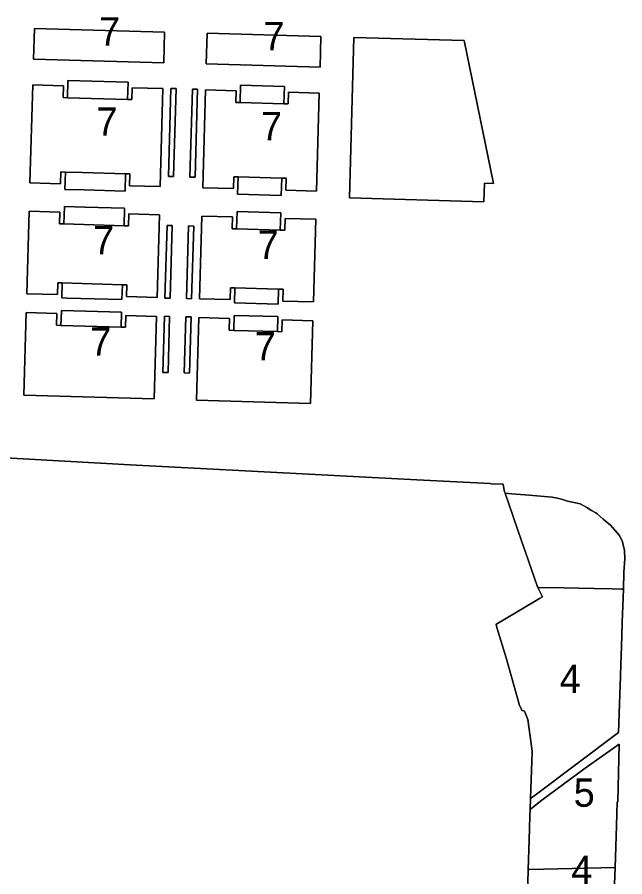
# Model space of a CAD drawing. Extents: x 598968 to 613553, y 4409678 to 4430833.
# Drawn here: x 607451 to 607708.4, y 4415273.1 to 4415637.2 of the extents above; entities that cross this region are included whole.
import ezdxf

# ---------------------------------------------------------------- set-up
doc = ezdxf.new("R2010")
doc.units = 0
for name, color, linetype in [('1', 7, 'Continuous'), ('ZONA 4. CASES UNIFAMILIRAS AÏLLADES EN PARCEL.LES', 7, 'Continuous'), ('ZONA 5. CASES UNIFAMILIARS EN RENGLE', 7, 'Continuous'), ('ZONA 7. CONJUNTS AMB ORDENACIONS ESPECÍFIQUES', 7, 'Continuous')]:
    doc.layers.add(name, color=color, linetype=linetype)

msp = doc.modelspace()

# ---------------------------------------------------------------- linework, layer by layer
at = {"layer": '1'}
for points in [[(607458.2278, 4415632.5068), (607513.3874, 4415630.9511), (607513.0173, 4415617.9598), (607457.8614, 4415619.5121)], [(607531.3978, 4415630.4394), (607579.6165, 4415629.0809), (607579.6281, 4415629.0806), (607579.2619, 4415616.0906), (607531.0172, 4415617.4505)], [(607593.6261, 4415628.6869), (607640.3951, 4415627.3559), (607652.7347, 4415566.7745), (607648.9096, 4415566.9135), (607648.6255, 4415559.0949), (607591.6906, 4415560.7152)], [(607640.3951, 4415627.3559), (607593.6261, 4415628.6869), (607591.6906, 4415560.7152), (607648.6255, 4415559.0949), (607648.9096, 4415566.9135), (607652.7347, 4415566.7745)], [(607472.4602, 4415610.4767), (607497.9495, 4415609.7512), (607497.7403, 4415602.4044), (607499.5895, 4415602.3518), (607499.7318, 4415607.3496), (607512.7264, 4415606.9798), (607511.5453, 4415565.4971), (607498.5506, 4415565.8669), (607498.693, 4415570.8648), (607496.8437, 4415570.9175), (607496.6345, 4415563.5705), (607479.4003, 4415564.0609), (607471.159, 4415564.2955), (607471.3544, 4415571.6428), (607469.5051, 4415571.6955), (607469.3628, 4415566.6976), (607456.3681, 4415567.0674), (607457.5484, 4415608.5198), (607470.5439, 4415608.1766), (607470.4017, 4415603.1824), (607472.2509, 4415603.1297)], [(607497.7403, 4415602.4044), (607497.9495, 4415609.7512), (607472.4602, 4415610.4767), (607472.2509, 4415603.1297)], [(607517.2167, 4415569.6873), (607515.0176, 4415569.75), (607516.0793, 4415607.0345), (607518.2783, 4415606.9718)], [(607518.2783, 4415606.9718), (607516.0793, 4415607.0345), (607515.0176, 4415569.75), (607517.2167, 4415569.6873)], [(607545.6296, 4415608.3943), (607564.1719, 4415607.8667), (607563.9626, 4415600.5197), (607565.8119, 4415600.4671), (607565.9542, 4415605.465), (607578.9488, 4415605.0952), (607577.7676, 4415563.6124), (607564.773, 4415563.9823), (607564.9153, 4415568.9802), (607563.0661, 4415569.0329), (607562.8569, 4415561.6859), (607544.3147, 4415562.2135), (607544.5238, 4415569.5604), (607542.6746, 4415569.6131), (607542.5323, 4415564.6153), (607529.5377, 4415564.985), (607530.7189, 4415606.4678), (607543.7134, 4415606.0979), (607543.5711, 4415601.1001), (607545.4204, 4415601.0474)], [(607563.9626, 4415600.5197), (607564.1719, 4415607.8667), (607545.6296, 4415608.3943), (607545.4204, 4415601.0474)], [(607526.313, 4415569.4285), (607524.1139, 4415569.4911), (607525.1754, 4415606.7756), (607527.3745, 4415606.713)], [(607527.3745, 4415606.713), (607525.1754, 4415606.7756), (607524.1139, 4415569.4911), (607526.313, 4415569.4285)], [(607496.8437, 4415570.9175), (607478.6707, 4415571.4346), (607471.3544, 4415571.6428), (607471.159, 4415564.2955), (607479.4003, 4415564.0609), (607496.6345, 4415563.5705)], [(607563.0661, 4415569.0329), (607544.5238, 4415569.5604), (607544.3147, 4415562.2135), (607562.8569, 4415561.6859)], [(607470.9374, 4415556.999), (607479.5455, 4415556.754), (607496.4268, 4415556.2735), (607496.2176, 4415548.9266), (607498.0668, 4415548.8739), (607498.2091, 4415553.8719), (607511.2037, 4415553.5021), (607510.2075, 4415518.5166), (607497.2129, 4415518.8865), (607497.3553, 4415523.8844), (607495.506, 4415523.9371), (607495.3253, 4415517.5897), (607472.108, 4415518.2504), (607469.8359, 4415518.3151), (607470.0167, 4415524.6624), (607468.1674, 4415524.7151), (607468.0251, 4415519.7171), (607455.0304, 4415520.087), (607456.0266, 4415555.0724), (607469.0213, 4415554.7025), (607468.879, 4415549.7046), (607470.7282, 4415549.652)], [(607496.2176, 4415548.9266), (607496.4268, 4415556.2735), (607479.5455, 4415556.754), (607470.9374, 4415556.999), (607470.7282, 4415549.652), (607479.2166, 4415549.4105)], [(607544.1069, 4415554.9166), (607562.6491, 4415554.389), (607562.4399, 4415547.042), (607564.2892, 4415546.9894), (607564.4315, 4415551.9872), (607577.426, 4415551.6175), (607576.4299, 4415516.632), (607563.4353, 4415517.0018), (607563.5776, 4415521.9997), (607561.7284, 4415522.0524), (607561.5476, 4415515.705), (607543.0054, 4415516.2327), (607543.1861, 4415522.5801), (607541.3368, 4415522.6327), (607541.1946, 4415517.6348), (607528.2, 4415518.0046), (607529.1962, 4415552.9901), (607542.1907, 4415552.6202), (607542.0485, 4415547.6223), (607543.8976, 4415547.5697)], [(607562.4399, 4415547.042), (607562.6491, 4415554.389), (607544.1069, 4415554.9166), (607543.8976, 4415547.5697)], [(607516.6275, 4415548.996), (607514.4285, 4415549.0586), (607513.5518, 4415518.2686), (607515.7509, 4415518.206)], [(607515.7509, 4415518.206), (607513.5518, 4415518.2686), (607514.4285, 4415549.0586), (607516.6275, 4415548.996)], [(607525.7237, 4415548.7371), (607523.5247, 4415548.7997), (607522.6481, 4415518.0125), (607524.8472, 4415517.95)], [(607525.7237, 4415548.7371), (607524.8472, 4415517.95), (607522.6481, 4415518.0125), (607523.5247, 4415548.7997)], [(607495.506, 4415523.9371), (607474.3119, 4415524.5402), (607470.0167, 4415524.6624), (607469.8359, 4415518.3151), (607472.108, 4415518.2504), (607495.3253, 4415517.5897)], [(607561.7284, 4415522.0524), (607543.1861, 4415522.5801), (607543.0054, 4415516.2327), (607561.5476, 4415515.705)], [(607454.8027, 4415512.0903), (607467.7975, 4415511.7204), (607467.6551, 4415506.7226), (607469.5044, 4415506.6699), (607469.6742, 4415512.6383), (607469.685, 4415513.0172), (607469.8366, 4415513.0129), (607495.1744, 4415512.2919), (607494.9937, 4415505.9446), (607496.8429, 4415505.8919), (607496.9852, 4415510.8898), (607509.9799, 4415510.52), (607508.9836, 4415475.5346), (607453.8065, 4415477.1049)], [(607494.9937, 4415505.9446), (607495.1744, 4415512.2919), (607469.8366, 4415513.0129), (607469.685, 4415513.0172), (607469.6742, 4415512.6383), (607469.5044, 4415506.6699)], [(607515.5318, 4415510.512), (607513.3327, 4415510.5747), (607512.6553, 4415486.7845), (607514.854, 4415486.709)], [(607514.854, 4415486.709), (607512.6553, 4415486.7845), (607513.3327, 4415510.5747), (607515.5318, 4415510.512)], [(607524.628, 4415510.2532), (607522.4289, 4415510.3157), (607521.7515, 4415486.5257), (607523.9507, 4415486.4654)], [(607523.9507, 4415486.4654), (607521.7515, 4415486.5257), (607522.4289, 4415510.3157), (607524.628, 4415510.2532)], [(607542.8546, 4415510.9349), (607561.3968, 4415510.4072), (607561.2161, 4415504.0599), (607563.0653, 4415504.0072), (607563.2076, 4415509.0052), (607576.2022, 4415508.6353), (607575.206, 4415473.6499), (607526.9762, 4415475.0225), (607527.9724, 4415510.0079), (607540.9669, 4415509.6381), (607540.8246, 4415504.6402), (607542.6738, 4415504.5876)], [(607561.2161, 4415504.0599), (607561.3968, 4415510.4072), (607542.8546, 4415510.9349), (607542.6738, 4415504.5876)], [(607707.7901, 4415394.9734), (607708.03, 4415402.1033), (607708.39, 4415407.8433), (607708.31, 4415411.3332), (607707.615, 4415414.3728), (607707.48, 4415414.9632), (607706.19, 4415417.7231), (607702.38, 4415422.073), (607699.2701, 4415424.6629), (607696.6286, 4415426.8626), (607696.1601, 4415427.2528), (607694.3101, 4415428.3528), (607692.3601, 4415429.5027), (607689.4202, 4415431.0626), (607683.5602, 4415432.4325), (607682.5102, 4415432.8625), (607680.3703, 4415433.3325), (607677.5903, 4415433.9823), (607667.8304, 4415434.7822), (607660.5105, 4415435.282), (607657.6822, 4415435.6), (607664.629, 4415415.4382), (607666.2658, 4415410.6878), (607671.211, 4415396.3354), (607671.5308, 4415395.6974), (607672.0125, 4415395.6878), (607672.0105, 4415395.6927), (607682.6935, 4415395.4773), (607688.9303, 4415395.3529), (607695.3387, 4415395.2302), (607703.0001, 4415395.0833), (607707.012, 4415394.9913)]]:
    msp.add_lwpolyline(points, close=True, dxfattribs=at)
for points in [[(607440.744, 4415450.8464), (607498.8447, 4415447.588), (607547.6036, 4415445.0498), (607620.2272, 4415441.2313), (607651.3138, 4415439.6642), (607651.6411, 4415439.6471), (607656.8517, 4415439.3747), (607657.0316, 4415438.4628), (607657.481, 4415436.184), (607657.6822, 4415435.6), (607660.5105, 4415435.282), (607667.8304, 4415434.7822), (607677.5903, 4415433.9823), (607680.3703, 4415433.3325), (607682.5102, 4415432.8625), (607683.5602, 4415432.4325), (607689.4202, 4415431.0626), (607692.3601, 4415429.5027), (607694.3101, 4415428.3528), (607696.1601, 4415427.2528), (607696.6286, 4415426.8626), (607699.2701, 4415424.6629), (607702.38, 4415422.073), (607706.19, 4415417.7231), (607707.48, 4415414.9632), (607707.615, 4415414.3728), (607708.31, 4415411.3332), (607708.39, 4415407.8433), (607708.03, 4415402.1033), (607707.7901, 4415394.9734), (607707.3301, 4415380.7736), (607707.0002, 4415370.5837), (607706.7602, 4415363.3538), (607706.5781, 4415357.9646), (607706.3202, 4415350.3339), (607705.6903, 4415334.2141), (607670.3508, 4415307.7637), (607668.4491, 4415306.3145), (607668.304, 4415301.7194), (607668.381, 4415301.769), (607673.2408, 4415305.5338), (607691.5925, 4415319.1472), (607705.9503, 4415329.3341), (607705.4404, 4415304.8544), (607705.1204, 4415304.8644), (607704.9204, 4415294.7445), (607704.2805, 4415277.1346), (607703.7565, 4415263.0431)], [(607667.3182, 4415270.4899), (607667.4999, 4415276.2469), (607667.8955, 4415288.7782), (607668.2133, 4415298.8449), (607668.304, 4415301.7194), (607668.4491, 4415306.3145), (607668.8282, 4415318.324), (607668.8283, 4415318.3271), (607668.9383, 4415321.8136), (607669.0824, 4415326.3758), (607667.3175, 4415339.7978), (607665.9547, 4415343.3497), (607665.5451, 4415343.4223), (607664.7508, 4415343.5632), (607664.5855, 4415343.9676), (607663.8185, 4415345.8451), (607663.6721, 4415346.1288), (607663.6115, 4415346.2463), (607658.1182, 4415365.8412), (607654.214, 4415378.6672), (607653.8195, 4415379.9631), (607653.7915, 4415380.0552), (607655.8477, 4415381.2634), (607656.1357, 4415381.4343), (607672.3119, 4415391.0336), (607673.5118, 4415391.7456), (607672.4148, 4415393.9341), (607672.4091, 4415393.9455), (607671.5308, 4415395.6974), (607671.211, 4415396.3354), (607666.2658, 4415410.6878), (607664.629, 4415415.4382), (607657.6822, 4415435.6), (607657.481, 4415436.184), (607657.0316, 4415438.4628), (607656.8517, 4415439.3747), (607651.6411, 4415439.6471), (607651.3138, 4415439.6642), (607620.2272, 4415441.2313), (607547.6036, 4415445.0498), (607498.8447, 4415447.588), (607440.744, 4415450.8464)]]:
    msp.add_lwpolyline(points, dxfattribs=at)
at = {"layer": 'ZONA 4. CASES UNIFAMILIRAS AÏLLADES EN PARCEL.LES'}
for points in [[(607707.7901, 4415394.9734), (607707.012, 4415394.9913), (607703.0001, 4415395.0833), (607695.3387, 4415395.2302), (607688.9303, 4415395.3529), (607682.6935, 4415395.4773), (607672.0105, 4415395.6927), (607672.0125, 4415395.6878), (607671.5308, 4415395.6974), (607672.4091, 4415393.9455), (607672.4148, 4415393.9341), (607673.5118, 4415391.7456), (607672.3119, 4415391.0336), (607656.1357, 4415381.4343), (607655.8477, 4415381.2634), (607653.7915, 4415380.0552), (607653.8195, 4415379.9631), (607654.214, 4415378.6672), (607658.1182, 4415365.8412), (607663.6115, 4415346.2463), (607663.6721, 4415346.1288), (607663.8185, 4415345.8451), (607664.5855, 4415343.9676), (607664.7508, 4415343.5632), (607665.5451, 4415343.4223), (607665.9547, 4415343.3497), (607667.3175, 4415339.7978), (607669.0824, 4415326.3758), (607668.9383, 4415321.8136), (607668.8283, 4415318.3271), (607668.8282, 4415318.324), (607668.4491, 4415306.3145), (607670.3508, 4415307.7637), (607705.6903, 4415334.2141), (607706.3202, 4415350.3339), (607706.5781, 4415357.9646), (607706.7602, 4415363.3538), (607707.0002, 4415370.5837), (607707.3301, 4415380.7736)], [(607667.1204, 4415264.2254), (607667.4355, 4415264.2114), (607669.5537, 4415264.1433), (607703.6158, 4415263.0477), (607703.7565, 4415263.0431), (607704.2805, 4415277.1346), (607667.8159, 4415276.2578), (607667.4999, 4415276.2469), (607667.3182, 4415270.4899)]]:
    msp.add_lwpolyline(points, close=True, dxfattribs=at)
at = {"layer": 'ZONA 5. CASES UNIFAMILIARS EN RENGLE'}
msp.add_lwpolyline([(607704.2805, 4415277.1346), (607704.9204, 4415294.7445), (607705.1204, 4415304.8644), (607705.4404, 4415304.8544), (607705.9503, 4415329.3341), (607691.5925, 4415319.1472), (607673.2408, 4415305.5338), (607668.381, 4415301.769), (607668.304, 4415301.7194), (607668.2133, 4415298.8449), (607667.8955, 4415288.7782), (607667.4999, 4415276.2469), (607667.8159, 4415276.2578)], close=True, dxfattribs=at)
at = {"layer": 'ZONA 7. CONJUNTS AMB ORDENACIONS ESPECÍFIQUES'}
for points in [[(607513.3874, 4415630.9511), (607458.2278, 4415632.5068), (607457.8614, 4415619.5121), (607513.0173, 4415617.9598)], [(607579.6281, 4415629.0806), (607579.6165, 4415629.0809), (607531.3978, 4415630.4394), (607531.0172, 4415617.4505), (607579.2619, 4415616.0906)], [(607472.2509, 4415603.1297), (607470.4017, 4415603.1824), (607470.5439, 4415608.1766), (607457.5484, 4415608.5198), (607456.3681, 4415567.0674), (607469.3628, 4415566.6976), (607469.5051, 4415571.6955), (607471.3544, 4415571.6428), (607478.6707, 4415571.4346), (607496.8437, 4415570.9175), (607498.693, 4415570.8648), (607498.5506, 4415565.8669), (607511.5453, 4415565.4971), (607512.7264, 4415606.9798), (607499.7318, 4415607.3496), (607499.5895, 4415602.3518), (607497.7403, 4415602.4044)], [(607545.4204, 4415601.0474), (607543.5711, 4415601.1001), (607543.7134, 4415606.0979), (607530.7189, 4415606.4678), (607529.5377, 4415564.985), (607542.5323, 4415564.6153), (607542.6746, 4415569.6131), (607544.5238, 4415569.5604), (607563.0661, 4415569.0329), (607564.9153, 4415568.9802), (607564.773, 4415563.9823), (607577.7676, 4415563.6124), (607578.9488, 4415605.0952), (607565.9542, 4415605.465), (607565.8119, 4415600.4671), (607563.9626, 4415600.5197)], [(607470.7282, 4415549.652), (607468.879, 4415549.7046), (607469.0213, 4415554.7025), (607456.0266, 4415555.0724), (607455.0304, 4415520.087), (607468.0251, 4415519.7171), (607468.1674, 4415524.7151), (607470.0167, 4415524.6624), (607474.3119, 4415524.5402), (607495.506, 4415523.9371), (607497.3553, 4415523.8844), (607497.2129, 4415518.8865), (607510.2075, 4415518.5166), (607511.2037, 4415553.5021), (607498.2091, 4415553.8719), (607498.0668, 4415548.8739), (607496.2176, 4415548.9266), (607479.2166, 4415549.4105)], [(607543.8976, 4415547.5697), (607542.0485, 4415547.6223), (607542.1907, 4415552.6202), (607529.1962, 4415552.9901), (607528.2, 4415518.0046), (607541.1946, 4415517.6348), (607541.3368, 4415522.6327), (607543.1861, 4415522.5801), (607561.7284, 4415522.0524), (607563.5776, 4415521.9997), (607563.4353, 4415517.0018), (607576.4299, 4415516.632), (607577.426, 4415551.6175), (607564.4315, 4415551.9872), (607564.2892, 4415546.9894), (607562.4399, 4415547.042)], [(607469.5044, 4415506.6699), (607467.6551, 4415506.7226), (607467.7975, 4415511.7204), (607454.8027, 4415512.0903), (607453.8065, 4415477.1049), (607508.9836, 4415475.5346), (607509.9799, 4415510.52), (607496.9852, 4415510.8898), (607496.8429, 4415505.8919), (607494.9937, 4415505.9446)], [(607542.6738, 4415504.5876), (607540.8246, 4415504.6402), (607540.9669, 4415509.6381), (607527.9724, 4415510.0079), (607526.9762, 4415475.0225), (607575.206, 4415473.6499), (607576.2022, 4415508.6353), (607563.2076, 4415509.0052), (607563.0653, 4415504.0072), (607561.2161, 4415504.0599)]]:
    msp.add_lwpolyline(points, close=True, dxfattribs=at)

# ---------------------------------------------------------------- texts
at = {"layer": 'ZONA 4. CASES UNIFAMILIRAS AÏLLADES EN PARCEL.LES'}
for p in [(607680.7908, 4415351.006), (607685.7005, 4415270.0888)]:
    msp.add_text('4', height=12, dxfattribs=at).set_placement(p)
at = {"layer": 'ZONA 5. CASES UNIFAMILIARS EN RENGLE'}
msp.add_text('5', height=12, dxfattribs=at).set_placement((607686.7251, 4415302.7905))
at = {"layer": 'ZONA 7. CONJUNTS AMB ORDENACIONS ESPECÍFIQUES'}
for p in [(607485.6244, 4415625.2333), (607555.3226, 4415623.265), (607484.5472, 4415587.0085), (607554.2433, 4415585.0401), (607483.1171, 4415536.7945), (607552.813, 4415534.811), (607481.8932, 4415493.8125), (607551.5892, 4415491.8289)]:
    msp.add_text('7', height=12, dxfattribs=at).set_placement(p)

doc.saveas('drawing.dxf')
